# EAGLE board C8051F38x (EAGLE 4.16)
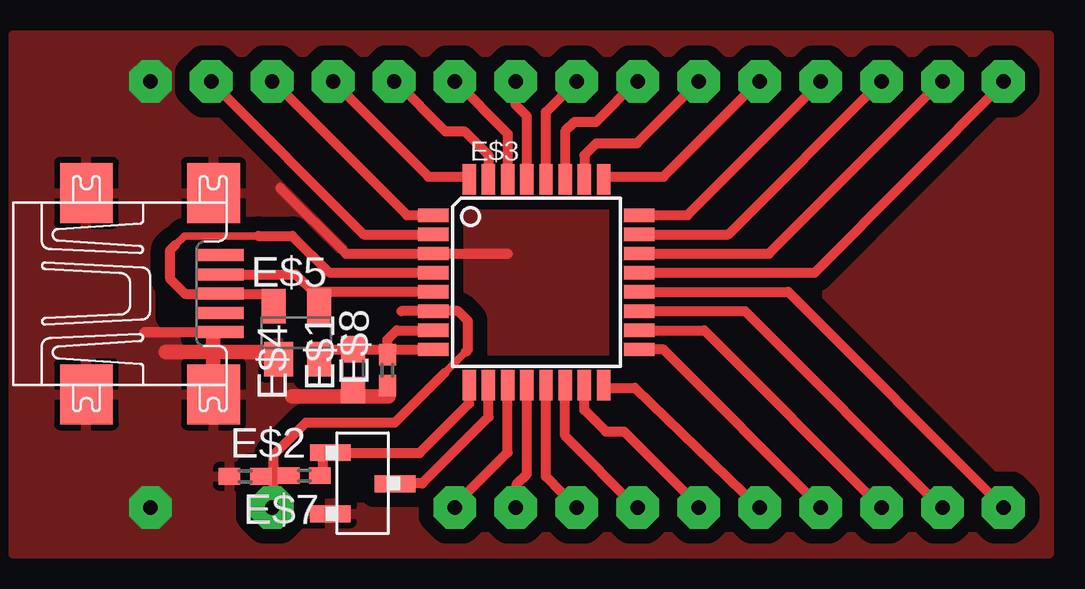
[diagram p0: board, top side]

No outline drawn. Coordinates in mm, seen from the top.
Copper layers (1*16): Top 0.035mm / dielectric 1.5mm / Bottom 0.035mm
Design rules "default": minimum track width 10mil, minimum drill 24mil, track to track 8mil, track to pad 8mil, pad to pad 8mil, via to via 8mil, smd to smd 8mil, copper to edge 40mil, drill to drill 8mil, minimum pad ring 10mil, minimum via ring 8mil, stop-mask expansion 4mil, vias tented up to drill 0mil, thermal gap 10mil

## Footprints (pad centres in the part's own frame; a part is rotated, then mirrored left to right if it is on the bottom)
C0603 = smd 1.1 x 1: 1 -0.85,0; 2 0.85,0
C0402 = smd 0.9 x 0.7: 1 -0.65,0; 2 0.65,0
TQFP32-08 = smd 1.27 x 0.559: 1 -4.293,2.8; 2 -4.293,2; 3 -4.293,1.2; 4 -4.293,0.4; 5 -4.293,-0.4; 6 -4.293,-1.2; 7 -4.293,-2; 8 -4.293,-2.8; 17 4.293,-2.8; 18 4.293,-2; 19 4.293,-1.2; 20 4.293,-0.4; 21 4.293,0.4; 22 4.293,1.2; 23 4.293,2; 24 4.293,2.8 | smd 0.559 x 1.27: 9 -2.8,-4.293; 10 -2,-4.293; 11 -1.2,-4.293; 12 -0.4,-4.293; 13 0.4,-4.293; 14 1.2,-4.293; 15 2,-4.293; 16 2.8,-4.293; 25 2.8,4.293; 26 2,4.293; 27 1.2,4.293; 28 0.4,4.293; 29 -0.4,4.293; 30 -1.2,4.293; 31 -2,4.293; 32 -2.8,4.293
UX60A-MB-5ST = smd 2 x 0.5: 1 2.25,1.6; 2 2.25,0.8; 3 2.25,0; 4 2.25,-0.8; 5 2.25,-1.6 | smd 2.2 x 2.5: M1 -3.3,-4.2; M2 -3.3,4.2; M3 2,4.2; M4 2,-4.2
SOT143 = smd 1.2 x 1.44: 1 -0.75,-1.1 | smd 1 x 1.44: 2 0.95,-1.1; 3 0.95,1.1; 4 -0.95,1.1
HEADER3S = smd 0.7 x 1.7: P$1 1.27,1.35; P$3 -1.28,1.35; P$4 -0.03,-1.35

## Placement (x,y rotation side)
E$1  [C0603]  14.17,7.66 90 top
E$2  [C0402]  9.67,3.21 0 top
E$3  [TQFP32-08]  21.81,11.3 0 top
E$4  [UX60A-MB-5ST]  6.35,10.83 0 top
E$5  [SOT143]  11.81,9.2 0 top
E$6  [HEADER3S]  14.57,2.93 90 top
E$7  [C0402]  12.14,3.24 180 top
E$8  [C0402]  15.6,7.64 90 top

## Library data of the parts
E$1 E$2 E$5 E$7 E$8 = ref-packages
E$3 = silabs-2
E$4 = con-hirose
E$6 = sb

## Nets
GND: E$2.1 E$4.M1 E$4.M2 E$4.M3 E$4.M4 E$5.1 E$6.P$3

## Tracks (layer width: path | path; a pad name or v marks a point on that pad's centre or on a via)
GND  (via drill 0.6 pad 1.78)
  Top 0.406: 20.61,12.5 13.87,12.5 11.13,15.24 | 5.48,9.23 8.35,9.23
  Top 0.61: 6.35,8.39 10.66,8.39 | 15.64,6.95 15.64,6.55 11.63,6.55 | 8.34,7.75 8.34,9.12
  other vias: 5.71,1.91 5.71,19.68
  pour Top (isolate 0.61): 0,0 43.18,0 43.18,21.59 0,21.59
S$1
  Top 0.406: 9.14,11.63 11.78,11.63 12.5,10.91 17.68,10.91
S$2  (via drill 0.6 pad 1.78)
  other vias: 26.04,1.91
S$3  (via drill 0.6 pad 1.78)
  other vias: 33.66,1.91
S$4  (via drill 0.6 pad 1.78)
  other vias: 18.41,1.91
S$5  (via drill 0.6 pad 1.78)
  other vias: 23.5,19.68
S$6  (via drill 0.6 pad 1.78)
  other vias: 18.41,19.68
S$7
  Top 0.406: 15.59,8.49 15.59,8.9 15.99,9.3 17.26,9.3
S$8
  Top 0.406: 17.41,9.3 17.31,9.3
S$10  (via drill 0.6 pad 1.78)
  other vias: 23.5,1.91
S$11
  Top 0.305: 10.23,13.24 7.14,13.24 6.75,12.85
  Top 0.406: 17.28,11.71 13.17,11.71 11.63,13.24 10.23,13.24 | 6.75,12.85 6.55,12.65 6.55,11.43 7.16,10.82 11.15,10.82
S$12
  Top 0.406: 17.11,13.3 14.61,13.3 8.21,19.7
S$13
  Top 0.406: 10.81,19.7 16.41,14.1 17.21,14.1
S$14
  Top 0.406: 16.08,2.91 17.05,2.91 19.82,5.68 19.82,6.82
S$15
  Top 0.406: 13.41,19.6 17.31,15.7 19.01,15.7
S$16
  Top 0.406: 19.81,15.7 19.81,16.6 18.81,17.6 18.01,17.6 15.91,19.7
S$17  (via drill 0.6 pad 1.78)
  other vias: 31.11,19.68
S$18  (via drill 0.6 pad 1.78)
  other vias: 33.66,19.68
S$19  (via drill 0.6 pad 1.78)
  other vias: 20.95,1.91
S$20  (via drill 0.6 pad 1.78)
  other vias: 28.57,1.91
S$21  (via drill 0.6 pad 1.78)
  other vias: 15.88,19.68
S$22  (via drill 0.6 pad 1.78)
  other vias: 36.2,19.68
S$23  (via drill 0.6 pad 1.78)
  other vias: 20.95,19.68
S$24  (via drill 0.6 pad 1.78)
  other vias: 13.34,19.68
S$25  (via drill 0.6 pad 1.78)
  other vias: 8.26,19.68
S$28  (via drill 0.6 pad 1.78)
  other vias: 38.73,19.68
S$29
  Top 0.406: 13.57,4.18 16.94,4.18 19.01,6.25 19.01,6.95
S$30
  Top 0.406: 23.01,6.9 23.01,4.9 25.99,1.9
S$31
  Top 0.406: 18.41,19.7 20.61,17.5 20.61,15.7
S$32  (via drill 0.6 pad 1.78)
  other vias: 26.04,19.68
S$33
  Top 0.406: 28.61,1.94 25.47,5.08 24.7,5.08 23.81,5.98 23.81,7.22
S$34  (via drill 0.6 pad 1.78)
  other vias: 28.57,19.68
S$35
  Top 0.406: 21.41,15.7 21.41,18.23 20.94,18.7 20.94,19.7
S$36
  Top 0.406: 22.21,15.7 22.21,18.4 23.51,19.7
S$37
  Top 0.406: 23.01,15.7 23.01,17.6 23.41,18 24.31,18 26.01,19.7
S$38  (via drill 0.6 pad 1.78)
  other vias: 41.27,19.68
S$39  (via drill 0.6 pad 1.78)
  other vias: 41.27,1.91
S$40  (via drill 0.6 pad 1.78)
  other vias: 38.73,1.91
S$41  (via drill 0.6 pad 1.78)
  other vias: 36.2,1.91
S$42  (via drill 0.6 pad 1.78)
  other vias: 31.11,1.91
S$43  (via drill 0.6 pad 1.78)
  other vias: 10.79,1.91
S$44
  Top 0.406: 23.81,15.7 23.81,16.6 24.31,17.1 26.01,17.1 28.61,19.7
S$45
  Top 0.406: 24.61,15.7 27.11,15.7 31.11,19.7
S$46
  Top 0.406: 13,8.5 17.28,8.5
S$47
  Top 0.406: 18.39,2 20.61,4.2 20.61,6.6
S$48
  Top 0.406: 20.99,1.9 20.99,2.88 21.41,3.3 21.41,6.9
S$49
  Top 0.406: 23.49,1.9 22.21,3.2 22.21,6.9
S$50
  Top 0.305: 17.98,7.52 18.86,8.4
  Top 0.406: 10.86,1.87 10.86,4.11 12.2,5.45 15.91,5.45 17.98,7.52 | 18.86,8.4 18.95,8.49 18.95,9.69 18.54,10.1 16.17,10.1
S$51
  Top 0.406: 31.09,1.9 25.91,6.9 24.61,6.9
S$52
  Top 0.406: 26.21,14.1 28.11,14.1 33.71,19.7
S$53
  Top 0.406: 26.21,13.3 29.81,13.3 36.21,19.7
S$54
  Top 0.406: 26.21,12.5 31.51,12.5 38.71,19.7
S$55
  Top 0.406: 26.21,11.7 33.41,11.7 41.35,19.68
S$56
  Top 0.406: 26.21,10.9 32.31,10.9 41.29,1.9
S$57
  Top 0.406: 26.21,10.1 30.51,10.1 38.79,1.8
S$58
  Top 0.406: 26.21,9.3 28.81,9.3 36.19,1.9
S$59
  Top 0.406: 26.21,8.5 27.11,8.5 33.69,1.9
S$60
  Top 0.406: 12.9,4.18 12.9,3.31
S$64  (via drill 0.6 pad 1.78)
  other vias: 10.79,19.68

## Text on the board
tDocu: C2CK | C2D | GND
